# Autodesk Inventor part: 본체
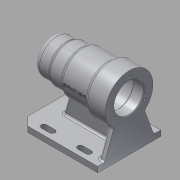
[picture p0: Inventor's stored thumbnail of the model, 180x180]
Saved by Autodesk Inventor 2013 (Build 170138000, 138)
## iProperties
Created: 2017-09
Part Number: 본체
Material: 알루미늄 6061
Document SubType Name: Modeling
Designer: Administrator
Density: 2.71 g/cm^3
Mass: 698.341 g
Surface Area: 709.394 cm^2
Volume: 257.691 cm^3
Author: Administrator
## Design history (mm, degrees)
sketch "스케치1"
  geometry: L1 (0, 0)-(-112, 0); L2 (-112, 22)-(-112, 34); L3 (-112, 34)-(-87, 34); L4 (-84, 31)-(-84, 30); L5 (-81.343, 30)-(-47.196, 30); L6 (-45, 30)-(-45, 30); L7 (-42, 27)-(-26.472, 27); L8 (-25, 27)-(-25, 28); L9 (-22, 25)-(-9, 25); L10 (0, 16)-(0, 0); L11 (-111, 21)-(-97, 21); L12 (-97, 21)-(-97, 21); L13 (-94, 24)-(-46, 24); L14 (-43, 21)-(-43, 21); L15 (-43, 21)-(-31.3, 21); L16 (-31, 20.7)-(-31, 17.5); L17 (-31, 17.5)-(-13.3, 17.5); L18 (-13, 17.2)-(-13, 16); L19 (-13, 16)-(-9.3, 16); L20 (-9, 15.7)-(-9, 10.5); L21 (-9, 10.5)-(-9, 10.5); L22 (-6, 7.5)-(-6, 0); L23 (-112, 22)-(-111, 21); A1 r 3 centre (-22, 28) between (-24.236, 26) and (-22, 25); A2 r 3 centre (-26.472, 24) between (-24.236, 26) and (-26.472, 27); A3 r 3 centre (-42, 30) between (-44.598, 28.5) and (-42, 27); A4 r 3 centre (-47.196, 27) between (-44.598, 28.5) and (-47.196, 30); A5 r 3 centre (-87, 31) between (-84.172, 32) and (-87, 34); A6 r 3 centre (-81.343, 33) between (-84.172, 32) and (-81.343, 30); A7 r 3 centre (-9, 7.5) between (-6, 7.5) and (-9, 10.5); A8 r 0.3 centre (-9.3, 15.7) between (-9, 15.7) and (-9.3, 16); A9 r 0.3 centre (-13.3, 17.2) between (-13, 17.2) and (-13.3, 17.5); A10 r 0.3 centre (-31.3, 20.7) between (-31, 20.7) and (-31.3, 21); A11 r 3 centre (-46, 21) between (-43, 21) and (-46, 24); A12 r 3 centre (-94, 21) between (-94, 24) and (-97, 21); A13 r 9 centre (-9, 16) between (0, 16) and (-9, 25); 9 further points
  constraints: 46 end point, 29 point on circle, 26 tangent, 23 point on line, 15 parallel, 13 centre point, 8 equal radius, 5 perpendicular, 1 collinear, 1 horizontal
  dimensions: "d0" = 112 distance of L1.start L1.end; "d1" = 25 distance of point (-25, 25) point (0, 25); "d2" = 45 distance between parallel lines of L6 L10; "d3" = 84 distance between parallel lines of L4 L10; "d4" = 50 diameter of L9 L1; "d5" = 54 diameter of L7 L1; "d6" = 60 diameter of L5 L1; "d7" = 68 diameter of L3 L1; "d8" = 3 radius of A1; "d9" = 3 radius of A5; "d10" = 42 diameter of L11 L1; "d11" = 48 diameter of L13 L1; "d12" = 42 diameter of L15 L1; "d13" = 35 diameter of L17 L1; "d14" = 32 diameter of L19 L1; "d16" = 21 diameter of L21 L1; "d17" = 15 distance of point (-112, 21) L11.end; "d18" = 54 distance of point (-97, 24) point (-43, 24); "d19" = 12 distance of L14.end point (-31, 21); "d20" = 18 distance of L16.end point (-13, 17.5); "d21" = 4 distance of L18.end point (-9, 16); "d22" = 3 distance of L20.end point (-6, 10.5); "d23" = 3 radius of A7; "d24" = 0.3 radius of A8; "d25" = 1 distance of L2.start point (-112, 21); "d26" = 1 distance of L11.start point (-112, 21) (= d25); "d27" = 9 radius of A13
revolve "회전1" sketch "스케치1" stored, may be unused: angle "d28" = 90 deg
node "작업 평면1"
sketch "스케치2"
  geometry: L1 (12, 45)-(112, 45); L2 (112, 45)-(112, -45); L3 (112, -45)-(12, -45); L4 (0, -33)-(0, 33); L5 (112, 34)-(112, -34) reference; L6 (12, 45)-(0, 33); L7 (0, -33)-(12, -45); 3 further points
  constraints: 12 end point, 4 point on line, 2 parallel, 1 horizontal, 1 perpendicular
  dimensions: "d30" = 0 distance between parallel lines of L2 L5; "d31" = 112 distance of point (0, 45) L1.end; "d32" = 90 distance of L1.end L2.end; "d33" = 45 distance from line of L1 point (0, 0); "d34" = 12 distance of L1.start point (0, 45); "d35" = 12 distance of L4.end point (0, 45) (= d34); "d36" = 12 distance of L4.start point (0, -45) (= d34); "d37" = 12 distance of L3.end point (0, -45) (= d36)
extrude "돌출1" join sketch "스케치2" distance "d38" = 8; taper "d39" = 0 deg
sketch "스케치3"
  geometry: L1 (62, -45)-(62, 45) reference; L2 (62, -35)-(26.008, -21.9); L3 (26.008, 21.9)-(62, 35); L4 (62, -35)-(62, 35); A1 r 34 centre (0, 0) between (26.008, -21.9) and (26.008, 21.9) reference; A2 r 34 centre (0, 0) between (26.008, -21.9) and (26.008, 21.9)
  constraints: 6 end point, 4 point on circle, 2 point on line, 1 centre point, 1 collinear, 1 concentric
  dimensions: "d40" = 10 distance of L1.start L2.start; "d41" = 10 distance of L1.end L3.end; "d42" = 110 deg angle of L2 L1; "d43" = 110 deg angle of L1 L3
extrude "돌출2" join sketch "스케치3" distance "d44" = 8; taper "d45" = 0 deg
sketch "스케치4"
  geometry: L1 (-12, -62)-(-112, -62) reference; L2 (-42, -27)-(-26.472, -27) reference; L3 (-81.343, -30)-(-47.196, -30) reference; L4 (-22, -62)-(-31.378, -27); L5 (0, -70)-(0, -62) reference; 1 further point
  constraints: 2 end point, 2 point on line
  dimensions: "d46" = 22 distance from line of L5 L4.start; "d47" = 105 deg angle of L1 L4
feature "리브1" sketch "스케치4" dims "d48" = 1, "d49" = 8, "d50" = 0, "d51" = 0, "d52" = 1, "d53" = 1
fillet "모깎기1" dims "d54" = 3
fillet "모깎기2" dims "d55" = 3
sketch "스케치5"
  geometry: L1 (112, 37.101)-(112, 45) reference; L2 (104, 7)-(104, 31.904) reference; L3 (24, 38)-(36, 38); L4 (24, 30)-(36, 30); L5 (76, 38)-(88, 38); L6 (76, 30)-(88, 30); A1 r 4 centre (24, 34) between (24, 38) and (24, 30); A2 r 4 centre (36, 34) between (36, 38) and (36, 30); A3 r 4 centre (76, 34) between (76, 38) and (76, 30); A4 r 4 centre (88, 34) between (88, 38) and (88, 30); 1 further point
  constraints: 8 end point, 8 point on circle, 4 centre point, 4 tangent, 3 parallel, 1 perpendicular
  dimensions: "d56" = 8 diameter of A1; "d58" = 8 diameter of A2; "d59" = 12 distance of A2.centre A1.centre; "d61" = 12 distance of A4.centre A3.centre; "d62" = 8 diameter of A3; "d63" = 8 diameter of A4; "d67" = 24 distance from line of L1 A4.centre; "d68" = 40 distance of A3.centre A2.centre; "d89" = 34 vertical distance of point (0, 0) A1.centre; "d90" = 34 vertical distance of point (0, 0) A2.centre; "d91" = 34 vertical distance of point (0, 0) A4.centre; "d92" = 34 vertical distance of point (0, 0) A3.centre
extrude "돌출3" cut sketch "스케치5" stored distance "d69" = 8; taper "d70" = 0 deg
sketch "스케치6" dims "d71" = 52
  geometry: C1 r 22 at (-70, 45) reference; A1 r 34 centre (-70, 45) between (-45.289, 68.353) and (-45.289, 21.647) reference; 2 further points
  constraints: 1 coincident, 1 horizontal alignment, 2 other
  dimensions: "d73" = 0 vertical distance of point (-96, 45) A1.centre
hole "구멍1" sketch "스케치6" at (-96, 45) diameter "d74" = 3.242; stored, may be unused: countersink angle "d78" = 90 deg, drill point angle "d80" = 118 deg; dims "d75" = 8, "d76" = 4, "d77" = 2, "d79" = 11
node "작업 평면2"
sketch "스케치7"
  geometry: L1 (47.408, 3.073)-(80.592, 3.073); L2 (80.592, 3.073)-(80.592, -3.073); L3 (80.592, -3.073)-(47.408, -3.073); L4 (47.408, -3.073)-(47.408, 3.073); L5 (64, 3.073)-(64, -3.073); L6 (47.408, 0)-(80.592, 0); L7 (112, 34)-(112, -24.711) reference; 1 further point
  constraints: 4 end point, 4 midpoint, 2 other
  dimensions: "d85" = 48 distance between parallel lines of L7 L5; "d86" = 0 distance from line of point (0, 0) L6; "d93" = 33.18318 distance of L1.start L1.end; "d94" = 6.14601 distance of L3.end L1.start
feature "엠보싱1" sketch "스케치7" dims "d87" = 0.5, "d88" = 0
node "솔리드1"
mirror "대칭1"
pattern_circular "원형 패턴1" dims angle "d82" = 360 deg
other parameters: "d84" = -34.5
